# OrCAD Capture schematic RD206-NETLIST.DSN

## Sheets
1 2: size A3
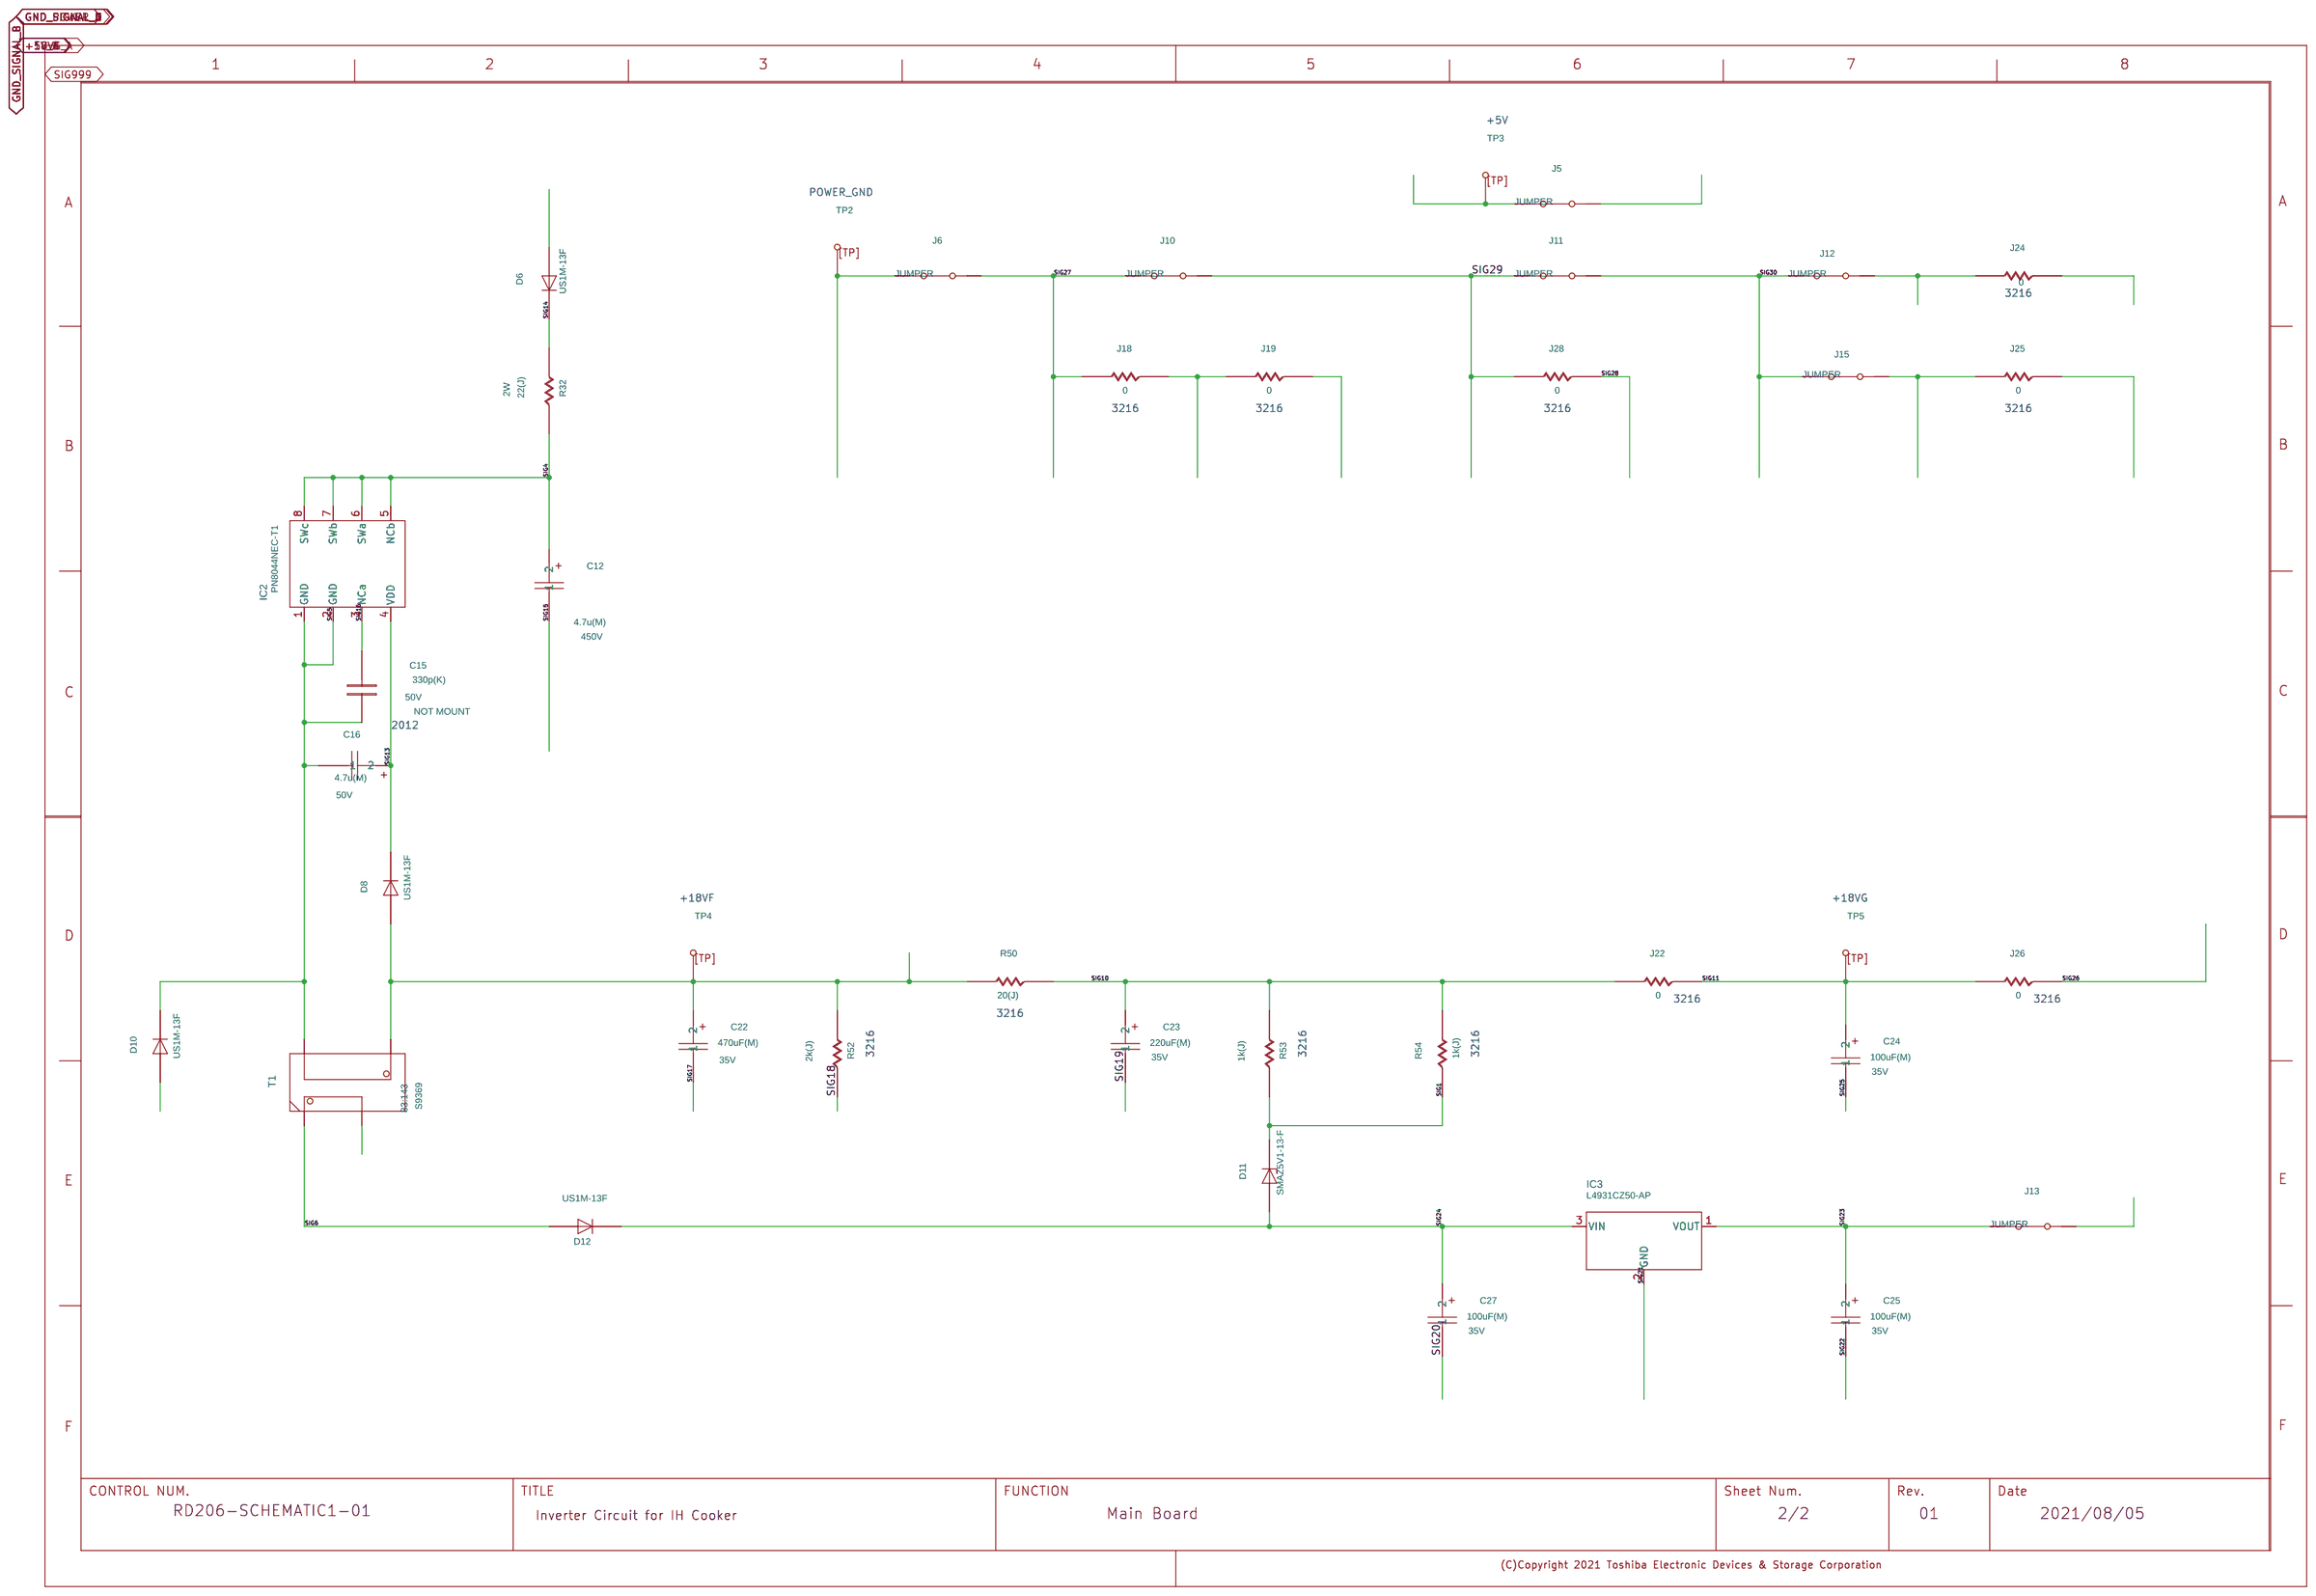
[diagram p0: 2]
2 1: size A3
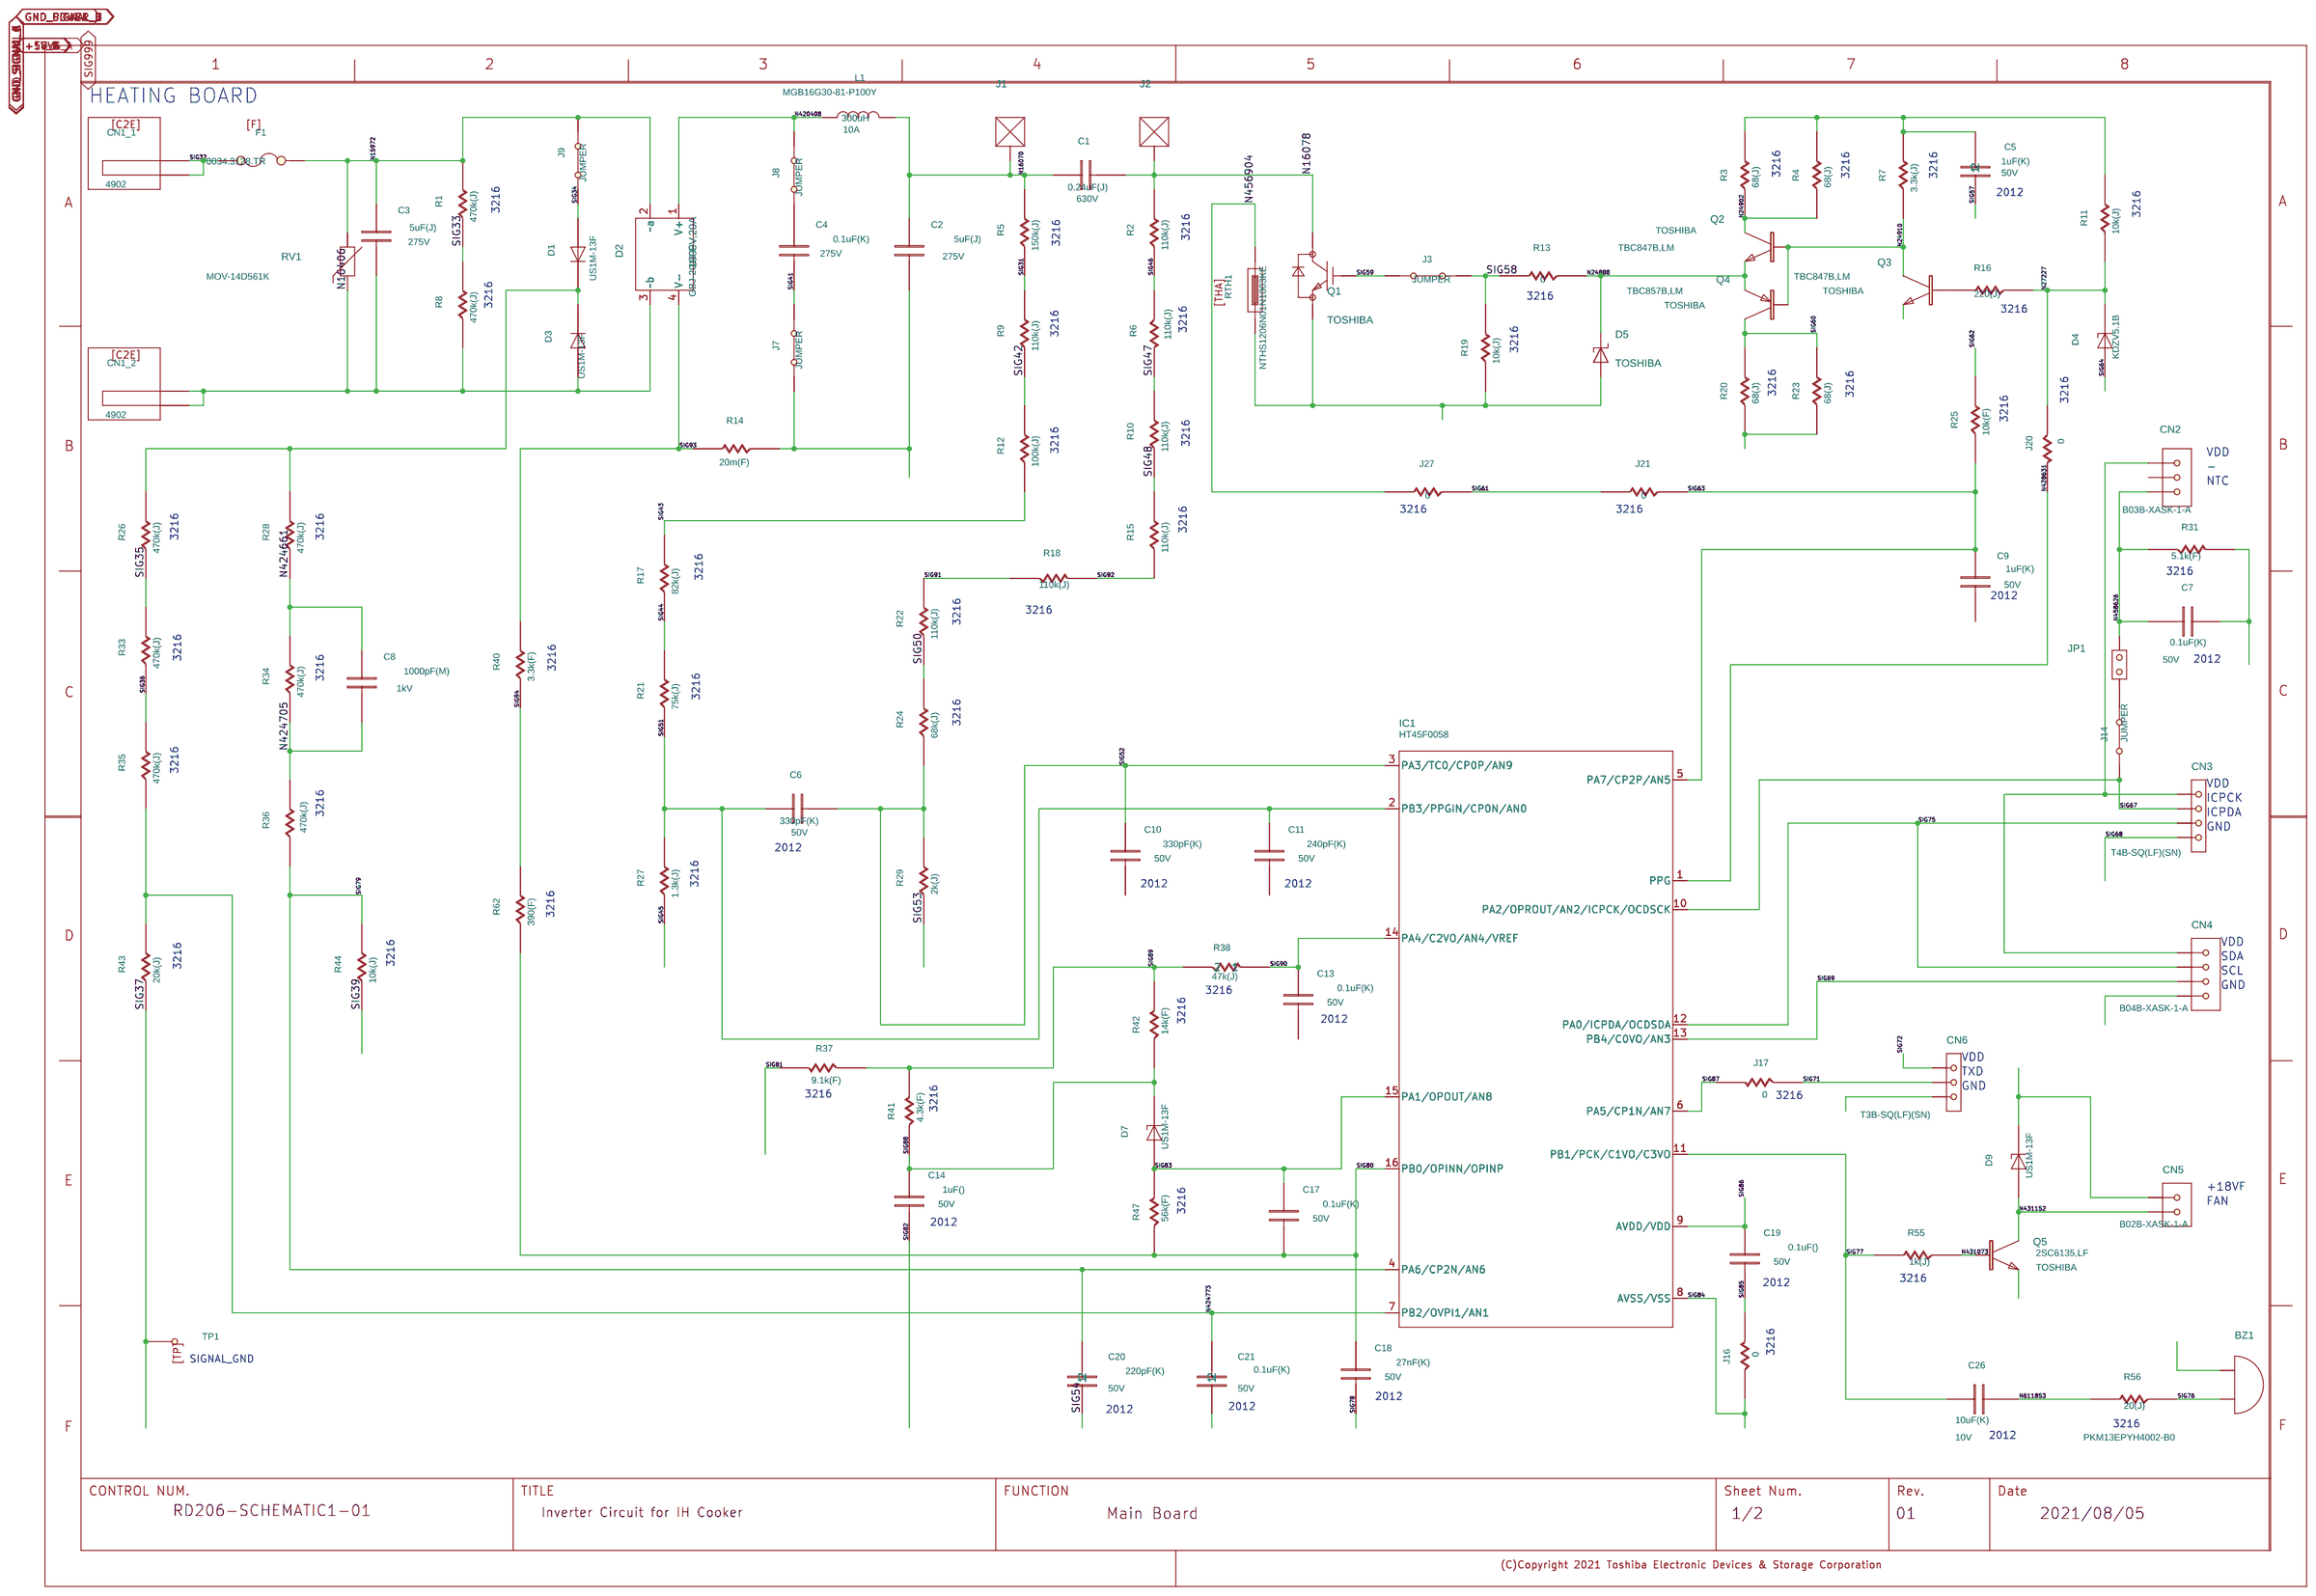
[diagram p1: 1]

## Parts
sheet 1
BZ1  PKM13EPYH4002-B0  [DIP]
C1  C
C2  C
C3  C
C4  C
C5  C
C6  C
C7  C
C8  C
C9  C
C10  C
C11  C
C13  C
C14  C
C17  C
C18  C
C19  C
C20  C
C21  C
C26  C
CN1_1  C2E
CN1_2  C2E
CN2  CON3S
CN3  T4B-SQ  [DIP]
CN4  B04B-XASK-1-A  [DIP]
CN5  B02B-XASK-1-A  [DIP]
CN6  T3B-SQ  [DIP]
D1  D
D2  GBJ2010  [SMA]
D3  D
D4  ZD
D5  CRZ18  [S-FLAT]
D7  ZD
D9  ZD
F1  F
IC1  HT45F0058
J1  OUT1
J2  OUT2
J3  JP
J7  JP
J8  JP
J9  JP
J14  JP
J16  R
J17  R
J20  R
J21  R
J27  R
JP1  T2B-SQ  [DIP]
L1  L
Q1  GT20N135SRA  [TO-247]
Q2  TBC847  [SOT-23]
Q3  TBC847  [SOT-23]
Q4  TBC857  [SOT-23]
Q5  2SC6135  [SOT-323]
R1  R
R2  R
R3  R
R4  R
R5  R
R6  R
R7  R
R8  R
R9  R
R10  R
R11  R
R12  R
R13  R
R14  R
R15  R
R16  R
R17  R
R18  R
R19  R
R20  R
R21  R
R22  R
R23  R
R24  R
R25  R
R26  R
R27  R
R28  R
R29  R
R31  R
R33  R
R34  R
R35  R
R36  R
R37  R
R38  R
R40  R
R41  R
R42  R
R43  R
R44  R
R47  R
R55  R
R56  R
R62  R
RTH1  THA
RV1  VARISTOR
TP1  TP
U?#1  WAKU_DEF100
sheet 2
C12  CP
C15  C
C16  CP
C22  CP
C23  CP
C24  CP
C25  CP
C27  CP
D6  D
D8  D
D10  D
D11  ZD
D12  D
IC2  PN8044NEC_T1
IC3  7805
J5  JP
J6  JP
J10  JP
J11  JP
J12  JP
J13  JP
J15  JP
J18  R
J19  R
J22  R
J24  R
J25  R
J26  R
J28  R
R32  R
R50  R
R52  R
R53  R
R54  R
T1  EE10
TP2  TP
TP3  TP
TP4  TP
TP5  TP
U?#2  WAKU_DEF100

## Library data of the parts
BZ1 = BUZZER: COMPONENTTYPE: 4; INSTANCENAME: INS611789; MANUFACTURER: Murata; PARTNAME: Part13801; VALUE2: D12.6xH6.9,4kHz
C1 = C: COMPONENTTYPE: 4; PARTNAME: Part13608; VAL1: 0.24uF(J); VAL2: 630V
C2 C3 = C: COMPONENTTYPE: 4; PARTNAME: Part13609; VAL1: 5uF(J); VAL2: 275V
C4 = C: COMPONENTTYPE: 4; PARTNAME: Part13606; VAL1: 0.1uF(K); VAL2: 275V
C5 = C#1: COMPONENTTYPE: 4; CaptureCellPackProp: C##1; PARTNAME: Part6003; VAL1: 1uF(K); VAL2: 50V
C6 C10 = C: COMPONENTTYPE: 4; PARTNAME: Part6003; VAL1: 330pF(K); VAL2: 50V
C7 C13 C17 = C: COMPONENTTYPE: 4; PARTNAME: Part6003; VAL1: 0.1uF(K); VAL2: 50V
C8 = C: COMPONENTTYPE: 4; PARTNAME: Part13607; VAL1: 1000pF(M); VAL2: 1kV
C9 = C: COMPONENTTYPE: 4; PARTNAME: Part6003; VAL1: 1uF(K); VAL2: 50V
C11 = C: COMPONENTTYPE: 4; PARTNAME: Part6003; VAL1: 240pF(K); VAL2: 50V
C14 = C: COMPONENTTYPE: 4; PARTNAME: Part6003; VAL1: 1uF(); VAL2: 50V
C18 = C: COMPONENTTYPE: 4; PARTNAME: Part6003; VAL1: 27nF(K); VAL2: 50V
C19 = C: COMPONENTTYPE: 4; PARTNAME: Part6003; VAL1: 0.1uF(); VAL2: 50V
C20 = C#1: COMPONENTTYPE: 4; CaptureCellPackProp: C##1; PARTNAME: Part6003; VAL1: 220pF(K); VAL2: 50V
C21 = C#1: COMPONENTTYPE: 4; CaptureCellPackProp: C##1; PARTNAME: Part6003; VAL1: 0.1uF(K); VAL2: 50V
C26 = C: COMPONENTTYPE: 4; PARTNAME: Part6003; VAL1: 10uF(K); VAL2: 10V
CN1_1 CN1_2 = C2E: COMPONENTTYPE: 4; PARTNAME: Part13901; VAL1: 4902; VAL3: 4902
CN2 = CON3S: COMPONENTTYPE: 4; PARTNAME: Part13910; VAL1: B03B-XASK-1-A; VAL3: B03B-XASK-1-A
CN3 = HEADER_4P: COMPONENTTYPE: 4; INSTANCENAME: INS493247; MANUFACTURER: JST; PARTNAME: Part13906; PART_NUMBER: T4B-SQ(LF)(SN); SAVECOUNT: 1; UPDATEDATE: 2021/07/15; UPDATETIME: 16:07:41; VAL1: T4B-SQ(LF)(SN); VAL3: T4B-SQ(LF)(SN); VALUE2: for Debugger,(NM)
CN4 = CON4S: COMPONENTTYPE: 4; INSTANCENAME: INS493000; MANUFACTURER: JST; PARTNAME: Part13904; SAVECOUNT: 1; UPDATEDATE: 2021/07/15; UPDATETIME: 16:07:41; VALUE2: to DISPLAY BOARD
CN5 = CON2S: COMPONENTTYPE: 4; INSTANCENAME: INS493353; MANUFACTURER: JST; PARTNAME: Part13902; SAVECOUNT: 1; UPDATEDATE: 2021/07/15; UPDATETIME: 16:07:41; VALUE2: to FAN
CN6 = HEADER_3P: COMPONENTTYPE: 4; INSTANCENAME: INS667453; MANUFACTURER: JST; PARTNAME: Part13908; PART_NUMBER: T3B-SQ(LF)(SN); SAVECOUNT: 1; UPDATEDATE: 2021/07/15; UPDATETIME: 16:07:41; VAL1: T3B-SQ(LF)(SN); VAL3: T3B-SQ(LF)(SN); VALUE2: for UART Debug
D1 D3 D6 D8 D10 D12 = D: COMPONENTTYPE: 4; PARTNAME: Part13451; VAL1: US1M-13F; VAL3: US1M-13F
D2 = D25XB: COMPONENTTYPE: 4; INSTANCENAME: INS420197; MANUFACTURER: DIODES; PARTNAME: Part13452; PART_NUMBER: GBJ-2010-F; SAVECOUNT: 1; UPDATEDATE: 2021/07/15; UPDATETIME: 16:07:41; VAL1: GBJ-2010-F; VAL3: GBJ-2010-F; VALUE2: 1000V,20A
D4 = ZD: COMPONENTTYPE: 4; PARTNAME: Part4291; VAL1: KDZV5.1B; VAL3: KDZV5.1B
D5 = DIODE_ZENER: COMPONENTTYPE: 4; INSTANCENAME: INS25179; MANUFACTURER: TOSHIBA; PARTNAME: Part4291
D7 D9 = ZD: COMPONENTTYPE: 4; PARTNAME: Part13451; VAL1: US1M-13F; VAL3: US1M-13F
F1 = F: COMPONENTTYPE: 4; PARTNAME: Part13701; VAL1: 0034.3128.TR; VAL2: 12.5A 250VAC; VAL3: 0034.3128.TR
IC1 = HT45F0058: COMPONENTTYPE: 4; PARTNAME: Part2183
J1 = TERMINAL: COMPONENTTYPE: 4; INSTANCENAME: INS418589; PARTNAME: Part13909; PART_NUMBER: for Heating coil; SAVECOUNT: 1; UPDATEDATE: 2021/07/15; UPDATETIME: 16:07:41
J2 = TERMINAL: COMPONENTTYPE: 4; INSTANCENAME: INS418681; PARTNAME: Part13909; PART_NUMBER: for Heating coil; SAVECOUNT: 1; UPDATEDATE: 2021/07/15; UPDATETIME: 16:07:41; VAL1: OUT1; VAL3: OUT1
J3 J6-J8 = JP: COMPONENTTYPE: 4; PARTNAME: Part13917; VAL1: JUMPER; VAL3: JUMPER
J5 J9-J11 J14 = JP: COMPONENTTYPE: 4; PARTNAME: Part13915; VAL1: JUMPER; VAL3: JUMPER
J16-J22 J24-J28 R13 = R: COMPONENTTYPE: 4; PARTNAME: Part4004; VAL1: 0
JP1 = HEADER: COMPONENTTYPE: 4; INSTANCENAME: INS520211; MANUFACTURER: JST; PARTNAME: Part13905; PART_NUMBER: T2B-SQ(LF)(SN); SAVECOUNT: 1; UPDATEDATE: 2021/07/15; UPDATETIME: 16:07:41; VAL1: T2B-SQ(LF)(SN); VAL3: T2B-SQ(LF)(SN)
L1 = L: COMPONENTTYPE: 4; PARTNAME: Part13301; VAL1: 300uH; VAL2: 10A; VAL3: MGB16G30-81-P100Y
Q1 = IGBT: COMPONENTTYPE: 4; INSTANCENAME: INS24255; MANUFACTURER: TOSHIBA; PARTNAME: Part13501; USERCOMPTEXT3: TOSHIBA
Q2 = 2SC: COMPONENTTYPE: 4; INSTANCENAME: INS24481; MANUFACTURER: TOSHIBA; PARTNAME: Part5004; PART_NUMBER: TBC847B,LM; USERCOMPTEXT3: TOSHIBA; VAL1: TBC847B,LM; VAL3: TBC847B,LM
Q3 = 2SC: COMPONENTTYPE: 4; INSTANCENAME: INS24374; MANUFACTURER: TOSHIBA; PARTNAME: Part5004; PART_NUMBER: TBC847B,LM; USERCOMPTEXT3: TOSHIBA; VAL1: TBC847B,LM; VAL3: TBC847B,LM
Q4 = 2SA: COMPONENTTYPE: 4; INSTANCENAME: INS24550; MANUFACTURER: TOSHIBA; PARTNAME: Part5004; PART_NUMBER: TBC857B,LM; USERCOMPTEXT3: TOSHIBA; VAL1: TBC857B,LM; VAL3: TBC857B,LM
Q5 = 2SC: COMPONENTTYPE: 4; INSTANCENAME: INS429563; MANUFACTURER: TOSHIBA; PARTNAME: Part13502; PART_NUMBER: 2SC6135,LF; USERCOMPTEXT3: TOSHIBA; VAL1: 2SC6135,LF; VAL3: 2SC6135,LF
R1 R8 R26 R28 R33-R36 = R: COMPONENTTYPE: 4; PARTNAME: Part4004; VAL1: 470k(J)
R2 R6 R9 R10 R15 R18 R22 = R: COMPONENTTYPE: 4; PARTNAME: Part4004; VAL1: 110k(J)
R3 R4 R20 R23 = R: COMPONENTTYPE: 4; PARTNAME: Part4004; VAL1: 68(J)
R5 = R: COMPONENTTYPE: 4; PARTNAME: Part4004; VAL1: 150k(J)
R7 = R: COMPONENTTYPE: 4; PARTNAME: Part4004; VAL1: 3.3k(J)
R11 R19 R44 = R: COMPONENTTYPE: 4; PARTNAME: Part4004; VAL1: 10k(J)
R12 = R: COMPONENTTYPE: 4; PARTNAME: Part4004; VAL1: 100k(J)
R14 = R: COMPONENTTYPE: 4; PARTNAME: Part13402; VAL1: 20m(F)
R16 = R: COMPONENTTYPE: 4; PARTNAME: Part4004; VAL1: 220(J)
R17 = R: COMPONENTTYPE: 4; PARTNAME: Part4004; VAL1: 82k(J)
R21 = R: COMPONENTTYPE: 4; PARTNAME: Part4004; VAL1: 75k(J)
R24 = R: COMPONENTTYPE: 4; PARTNAME: Part4004; VAL1: 68k(J)
R25 = R: COMPONENTTYPE: 4; PARTNAME: Part4004; VAL1: 10k(F)
R27 = R: COMPONENTTYPE: 4; PARTNAME: Part4004; VAL1: 1.3k(J)
R29 R52 = R: COMPONENTTYPE: 4; PARTNAME: Part4004; VAL1: 2k(J)
R31 = R: COMPONENTTYPE: 4; PARTNAME: Part4004; VAL1: 5.1k(F)
R37 = R: COMPONENTTYPE: 4; PARTNAME: Part4004; VAL1: 9.1k(F)
R38 = R#1: COMPONENTTYPE: 4; CaptureCellPackProp: R##1; PARTNAME: Part4004; VAL1: 47k(J)
R40 = R: COMPONENTTYPE: 4; PARTNAME: Part4004; VAL1: 3.3k(F)
R41 = R: COMPONENTTYPE: 4; PARTNAME: Part4004; VAL1: 4.3k(F)
R42 = R: COMPONENTTYPE: 4; PARTNAME: Part4004; VAL1: 14k(F)
R43 = R: COMPONENTTYPE: 4; PARTNAME: Part4004; VAL1: 20k(J)
R47 = R: COMPONENTTYPE: 4; PARTNAME: Part4004; VAL1: 56k(F)
R53-R55 = R: COMPONENTTYPE: 4; PARTNAME: Part4004; VAL1: 1k(J)
R50 R56 = R: COMPONENTTYPE: 4; PARTNAME: Part4004; VAL1: 20(J)
R62 = R: COMPONENTTYPE: 4; PARTNAME: Part4004; VAL1: 390(F)
RTH1 = THA: COMPONENTTYPE: 4; PARTNAME: Part3109; VAL1: NTHS1206N01N1003KE; VAL3: NTHS1206N01N1003KE
RV1 = VARISTOR: COMPONENTTYPE: 4; PARTNAME: Part13302; VAL1: MOV-14D561K; VAL3: MOV-14D561K
TP1-TP5 = TP: COMPONENTTYPE: 4; PARTNAME: Part13998
U?#1 = WAKU_DEF100: COMPONENTTYPE: 2; DATE: 2021/08/05; DRAWINGNUMBER: RD206-SCHEMATIC1-01; FUNCTION: Main Board; REVISION: 01; SHEETNUMBER: 1/2; TITLE: Inverter Circuit for IH Cooker; UPDATEDATE: 2021/08/05; UPDATETIME: 11:15:29
C12 = CP: COMPONENTTYPE: 4; PARTNAME: Part13601; VAL1: 4.7u(M); VAL2: 450V
C15 = C: COMPONENTTYPE: 4; NOTMOUNT: NOT MOUNT; PARTNAME: Part6003; VAL1: 330p(K); VAL2: 50V
C16 = CP: COMPONENTTYPE: 4; PARTNAME: Part13603; VAL1: 4.7u(M); VAL2: 50V
C22 = CP: COMPONENTTYPE: 4; PARTNAME: Part13601; VAL1: 470uF(M); VAL2: 35V
C23 = CP: COMPONENTTYPE: 4; PARTNAME: Part13604; VAL1: 220uF(M); VAL2: 35V
C24 C25 C27 = CP: COMPONENTTYPE: 4; PARTNAME: Part13605; VAL1: 100uF(M); VAL2: 35V
D11 = ZD: COMPONENTTYPE: 4; PARTNAME: Part13451; VAL1: SMAZ5V1-13-F; VAL3: SMAZ5V1-13-F
IC2 = PN8044NEC_T1: COMPONENTNAME: PN8044NEC-T1_PN8044NEC-T1.Normal_package; COMPONENTTYPE: 4; FUNCTION: PN8044NEC-T1_PN8044NEC-T1.Normal_package; PARTNAME: Part13001; VAL1: PN8044NEC-T1; VAL3: PN8044NEC-T1
IC3 = 7805: COMPONENTTYPE: 4; PARTNAME: Part13002; VAL1: L4931CZ50-AP; VAL3: L4931CZ50-AP
J12 J13 = JP: COMPONENTTYPE: 4; PARTNAME: Part13913; VAL1: JUMPER; VAL3: JUMPER
J15 = JP: COMPONENTTYPE: 4; PARTNAME: Part13911; VAL1: JUMPER; VAL3: JUMPER
R32 = R: COMPONENTTYPE: 4; PARTNAME: Part13401; VAL1: 22(J); VAL2: 2W
T1 = EE10: COMPONENTTYPE: 4; PARTNAME: Part13303; VAL1: 83:143; VAL3: S9369
U?#2 = WAKU_DEF100: COMPONENTTYPE: 2; DATE: 2021/08/05; DRAWINGNUMBER: RD206-SCHEMATIC1-01; FUNCTION: Main Board; REVISION: 01; SHEETNUMBER: 2/2; TITLE: Inverter Circuit for IH Cooker; UPDATEDATE: 2021/08/05; UPDATETIME: 11:15:29

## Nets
+5V_A: BZ1.1 C19.1 CN2.3 CN3.4 CN4.4 IC1.9(AVDD/VDD) J5.1 J13.2 TP3.1
+5V_B: CN6.3 J5.2 R25.1
+18VF: C22.1(2) CN5.2 D8.A D9.C R50.1 R52.1 T1.5 TP4.1
+18VG_A: C5.1(2) J26.2 R3.1 R4.1 R7.1 R11.1
GND_POWER: C2.2 D5.A(Anode) J6.1 J7.2 Q1.3(EMITTER) R14.2 R19.2 R20.2 R23.2 RTH1.1 TP2.1
GND_SIGNAL: J6.2 J10.1 J18.1
GND_SIGNAL_A: C9.2 C21.2(1) CN6.1 J10.2 J11.1 J28.1 R43.2 TP1.1
GND_SIGNAL_B: C12.2(1) C22.2(1) C23.2(1) C24.2(1) C25.2(1) C27.2(1) D10.A IC3.2(GND) J11.2 J12.1 J15.1 Q5.2(E) R52.2 T1.3
GND_SIGNAL_C: C13.2 C14.2 CN3.1 J12.2 J24.1 R37.1
GND_SIGNAL_D: C7.1 CN4.1 J24.2 R31.1
GND_SIGNAL_E: C5.2(1) D4.A J15.2 J25.1 Q3.2(E)
GND_SIGNAL_F: J25.2 R27.2 R29.2
GND_SIGNAL_G: C11.2
GND_SIGNAL_G (page 2): J18.2 J19.1
GND_SIGNAL_H: C4.1 C10.2 C18.2 J8.2 J19.2
GND_SIGNAL_I: C20.2(1) IC1.8(AVSS/VSS) J16.2 J28.2 R44.2
SIG1: D11.C R53.2 R54.2
SIG4: C12.1(2) IC2.5(NCb) IC2.6(SWa) IC2.7(SWb) IC2.8(SWc) R32.2
SIG5: C15.1 C16.2(1) D10.C IC2.1(GND) IC2.2(GND) T1.8
SIG6: D12.A T1.1
SIG10: C23.1(2) J22.1 R50.2 R53.1 R54.1
SIG11: C24.1(2) J22.2 J26.1 TP5.1
SIG13: C16.1(2) D8.C IC2.4(VDD)
SIG14: D6.C R32.1
SIG16: C15.2 IC2.3(NCa)
SIG23: C25.1(2) IC3.1(VOUT) J13.1
SIG24: C27.1(2) D11.A D12.C IC3.3(VIN)
SIG31: R5.2 R9.1
SIG32: CN1_1.1 CN1_1.2 F1.1
SIG33: R1.2 R8.1
SIG34: D1.A J9.2
SIG35: R26.2 R33.1
SIG36: R33.2 R35.1
SIG41: C4.2 J7.1
SIG42: R9.2 R12.1
SIG43: R12.2 R17.1
SIG44: R17.2 R21.1
SIG46: R2.2 R6.2
SIG47: R6.1 R10.1
SIG48: R10.2 R15.1
SIG50: R22.2 R24.1
SIG51: C6.1 C11.1 IC1.2(PB3/PPGIN/CP0N/AN0) R21.2 R27.1
SIG52: C6.2 C10.1 IC1.3(PA3/TC0/CP0P/AN9) R24.2 R29.1
SIG58: J3.2 R13.1 R19.1
SIG59: J3.1 Q1.1(GATE)
SIG60: Q4.3(C) R20.1 R23.1
SIG61: J21.1 J27.2
SIG63: C9.1 IC1.5(PA7/CP2P/AN5) J21.2 R25.2
SIG67: CN3.3 IC1.10(PA2/OPROUT/AN2/ICPCK/OCDSCK) J14.1
SIG69: CN4.2 IC1.13(PB4/C0VO/AN3)
SIG71: CN6.2 J17.2
SIG75: CN3.2 CN4.3 IC1.12(PA0/ICPDA/OCDSDA)
SIG76: BZ1.2 R56.2
SIG77: C26.1 IC1.11(PB1/PCK/C1VO/C3VO) R55.1
SIG79: C20.1(2) IC1.4(PA6/CP2N/AN6) R36.2 R44.1
SIG80: C17.2 C18.1 IC1.16(PB0/OPINN/OPINP) R47.2 R62.2
SIG83: C17.1 D7.A IC1.15(PA1/OPOUT/AN8) R47.1
SIG85: C19.2 J16.1
SIG87: IC1.6(PA5/CP1N/AN7) J17.1
SIG88: C14.1 D7.C R41.2 R42.2
SIG89: R37.2 R38.1(2) R41.1 R42.1
SIG90: C13.1 IC1.14(PA4/C2VO/AN4/VREF) R38.2(1)
SIG91: R18.2 R22.1
SIG92: R15.2 R18.1
SIG93: D2.4(V-) R14.1 R40.1
SIG94: R40.2 R62.1
SIG999: D1.C D3.C D6.A R26.1 R28.1
N02629: Q3.1(B) R16.1
N02633: J14.2 JP1.1
N15972: C3.1 D2.2(~a) F1.2 J9.1 R1.1 RV1.1
N16070: C1.1 C2.1 J1.1 L1.2 R5.1
N16078: C1.2 J2.1 Q1.2(COLLECTOR) R2.1
N16406: C3.2 CN1_2.1 CN1_2.2 D2.3(~b) D3.A R8.2 RV1.2
N24888: D5.C(Cathode) Q2.2(E) Q4.2(E) R13.2
N24902: Q2.3(C) R3.2 R4.2
N24910: Q2.1(B) Q3.3(C) Q4.1(B) R7.2
N27227: D4.C J20.2 R11.2 R16.2
N420408: D2.1(V+) J8.1 L1.1
N424661: C8.1 R28.2 R34.1
N424705: C8.2 R34.2 R36.1
N424773: C21.1(2) IC1.7(PB2/OVPI1/AN1) R35.2 R43.1
N428631: IC1.1(PPG) J20.1
N431073: Q5.1(B) R55.2
N431152: CN5.1 D9.A Q5.3(C)
N456904: J27.1 RTH1.2
N458626: C7.2 CN2.1 JP1.2 R31.2
N611853: C26.2 R56.1

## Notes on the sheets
sheet 1
- +5V
- POWER_GND
- 3216
- 3216
- 3216
- 3216
- 3216
- 2012
- +18VF
- +18VG
- 3216
- 3216
- 3216
- 3216
- 3216
- 3216
sheet 2
- HEATING BOARD
- 3216
- 3216
- 3216
- 2012
- 3216
- 3216
- 3216
- 3216
- 3216
- 3216
- 3216
- 3216
- 3216
- 3216
- 3216
- 3216
- 3216
- 3216
- 3216
- VDD
- 3216
- -
- NTC
- 3216
- 3216
- 3216
- 3216
- 3216
- 3216
- 3216
- 3216
- 2012
- 3216
- 2012
- 3216
- 3216
- 3216
- 3216
- 3216
- 3216
- ICPCK
- VDD
- ICPDA
- 3216
- GND
- 2012
- 3216
- 2012
- 2012
- 3216
- VDD
- SDA
- 3216
- 3216
- SCL
- 3216
- GND
- 3216
- 2012
- VDD
- GND
- TXD
- 3216
- 3216
- 3216
- +18VF
- FAN
- 2012
- 3216
- 2012
- 3216
- SIGNAL_GND
- 3216
- 2012
- 2012
- 2012
- 3216
- 2012
